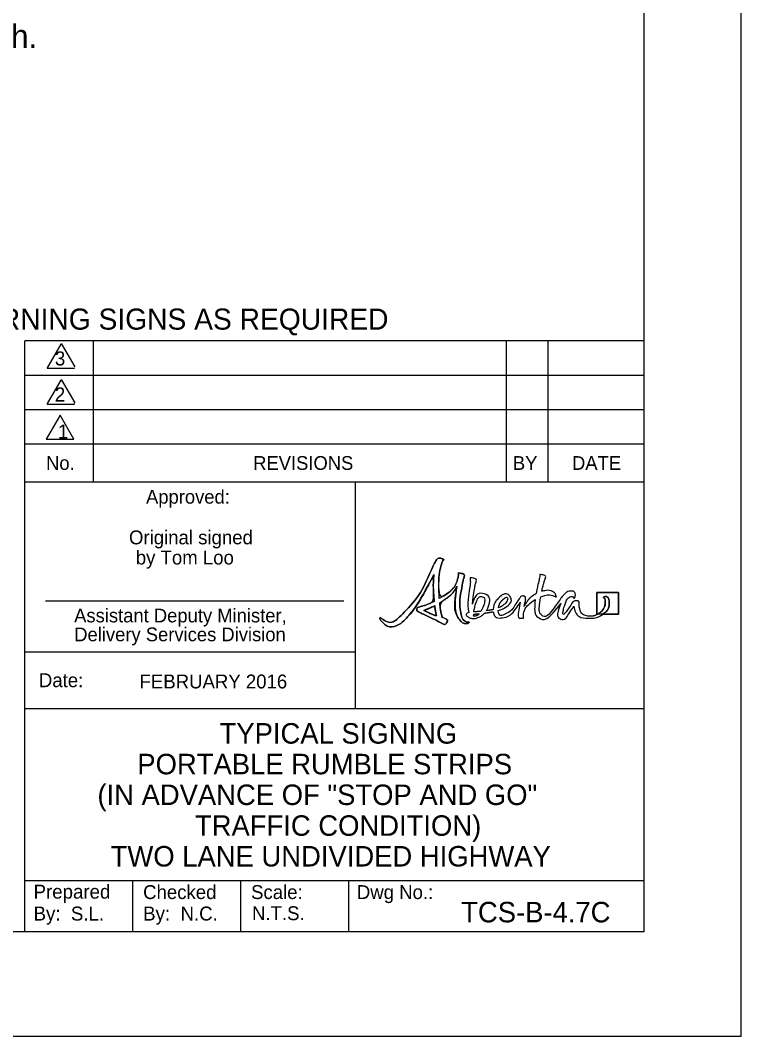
# Model space of a CAD drawing. Extents: x 1372 to 1588, y 125 to 404.
# Drawn here: x 1513.7 to 1588.1, y 125 to 229.9 of the extents above; entities that cross this region are included whole.
import ezdxf

# ---------------------------------------------------------------- set-up
doc = ezdxf.new("R2010")
doc.units = 0
for name, color, linetype in [('Level 1', 7, 'Continuous'), ('Level 10', 7, 'Continuous'), ('Level 22', 7, 'Continuous'), ('Level 44', 7, 'Continuous'), ('Level 45', 7, 'Continuous'), ('Level 53', 7, 'Continuous'), ('Level 60', 7, 'Continuous'), ('Level 63', 7, 'Continuous')]:
    doc.layers.add(name, color=color, linetype=linetype)

msp = doc.modelspace()

# ---------------------------------------------------------------- linework, layer by layer
at = {"layer": 'Level 1'}
for p, q in [((1514.18, 135.79), (1514.18, 182.27)), ((1548.25, 182.27), (1548.25, 158.85)), ((1514.18, 164.71), (1548.25, 164.71)), ((1514.18, 158.85), (1578.06, 158.85)), ((1514.18, 141.11), (1578.06, 141.11)), ((1525.32, 135.79), (1525.32, 141.11)), ((1536.45, 135.79), (1536.45, 141.11)), ((1547.59, 141.11), (1547.59, 135.79))]:
    msp.add_line(p, q, dxfattribs=at)
at = {"layer": 'Level 10'}
msp.add_line((1578.06, 182.27), (1578.06, 135.79), dxfattribs=at)
at = {"layer": 'Level 22'}
msp.add_line((1529.67, 135.79), (1529.67, 135.79), dxfattribs=at)
at = {"layer": 'Level 44'}
for p, q in [((1578.06, 196.82), (1514.18, 196.82)), ((1578.06, 193.27), (1514.18, 193.27)), ((1578.06, 189.72), (1514.18, 189.72)), ((1578.06, 186.18), (1514.18, 186.18)), ((1514.18, 182.27), (1578.06, 182.27))]:
    msp.add_line(p, q, dxfattribs=at)
msp.add_lwpolyline([(1517.8, 189.16), (1516.38, 186.69), (1519.22, 186.69)], close=True, dxfattribs=at)
at = {"layer": 'Level 45'}
msp.add_line((1548.25, 182.27), (1548.25, 182.27), dxfattribs=at)
at = {"layer": 'Level 53'}
msp.add_line((1573.82, 168.6), (1573.27, 168.6), dxfattribs=at)
msp.add_lwpolyline([(1573.82, 168.6), (1575.44, 168.6), (1575.44, 170.83), (1573.21, 170.83), (1573.21, 168.6), (1573.27, 168.6)], dxfattribs=at)
for points, degree in [([(1559.84, 167.79), (1559.6, 167.82), (1559.28, 168.15), (1559.19, 168.68), (1559.02, 169.65), (1559.12, 170.61), (1559.4, 172.03), (1559.45, 172.29), (1559.64, 172.76), (1559.05, 172.85), (1558.87, 172.88), (1558.97, 172.79), (1558.91, 172.54), (1558.69, 171.48), (1557.82, 170.72), (1556.95, 170.21), (1556.86, 171.42), (1556.9, 172.77), (1557.13, 173.59), (1557.32, 174.29), (1557.55, 174.16), (1557.27, 174.31), (1556.97, 174.46), (1556.65, 174.26), (1556.39, 173.74), (1556.13, 173.22), (1554.93, 170.4), (1553.02, 168.5), (1552.04, 167.53), (1551.16, 168.03), (1550.98, 168.18), (1550.83, 168.3), (1550.78, 168.12), (1550.96, 167.92), (1551.75, 167.07), (1552.91, 167.56), (1553.33, 167.98), (1554.49, 169.14), (1555.84, 171.64), (1556.39, 172.71), (1556.34, 172.11), (1556.32, 171.11), (1556.43, 169.93), (1555.84, 169.64), (1555.31, 169.47), (1555.06, 169.41), (1554.79, 169.34), (1554.62, 169.23), (1554.62, 169.1), (1554.61, 168.96), (1554.79, 168.85), (1555.06, 168.72), (1555.52, 168.5), (1556.9, 167.85), (1557.23, 167.65), (1557.52, 167.49), (1557.67, 167.62), (1557.75, 167.8), (1557.86, 168.03), (1557.56, 168.17), (1557.26, 168.26), (1557.14, 168.66), (1557.05, 169.19), (1556.99, 169.78), (1557.69, 170.21), (1558.38, 170.78), (1558.77, 171.5), (1558.67, 170.9), (1558.42, 168.87), (1559.06, 168.01), (1559.2, 167.82), (1559.51, 167.62), (1559.81, 167.65), (1559.96, 167.66), (1560.03, 167.76), (1560.02, 167.79), (1560, 167.82), (1559.92, 167.77), (1559.84, 167.79)], 3), ([(1556.95, 170.21), (1556.86, 171.42), (1556.9, 172.77), (1557.13, 173.59), (1557.32, 174.29), (1557.55, 174.16), (1557.27, 174.31), (1556.97, 174.46), (1556.65, 174.26), (1556.39, 173.74), (1556.13, 173.22), (1554.93, 170.4), (1553.02, 168.5), (1552.04, 167.53), (1551.16, 168.03), (1550.98, 168.18), (1550.83, 168.3), (1550.78, 168.12), (1550.96, 167.92), (1551.75, 167.07), (1552.91, 167.56), (1553.33, 167.98), (1554.49, 169.14), (1555.84, 171.64), (1556.39, 172.71)], 3), ([(1556.39, 172.71), (1556.34, 172.11), (1556.32, 171.11), (1556.43, 169.93)], 2), ([(1559.84, 167.79), (1559.6, 167.82), (1559.28, 168.15), (1559.19, 168.68), (1559.02, 169.65), (1559.12, 170.61), (1559.4, 172.03), (1559.45, 172.29), (1559.64, 172.76), (1559.05, 172.85), (1558.87, 172.88), (1558.97, 172.79), (1558.91, 172.54), (1558.69, 171.48), (1557.82, 170.72), (1556.95, 170.21)], 3), ([(1560.37, 169.63), (1560.42, 170.2), (1560.51, 170.89), (1560.64, 171.53), (1560.69, 171.8), (1560.88, 172.27), (1560.29, 172.36), (1560.11, 172.38), (1560.13, 172.3), (1560.15, 172.05), (1560.17, 171.71), (1559.8, 169.67), (1559.99, 168.77)], 3), ([(1567.53, 170.97), (1567.59, 171.27), (1567.67, 171.57), (1567.75, 171.86), (1567.82, 172.13), (1568.05, 172.6), (1567.47, 172.69), (1567.29, 172.71), (1567.36, 172.63), (1567.3, 172.38), (1567.19, 171.92), (1567.05, 171.33), (1566.95, 170.73)], 3), ([(1556.99, 169.78), (1557.69, 170.21), (1558.38, 170.78), (1558.77, 171.5)], 2), ([(1558.77, 171.5), (1558.67, 170.9), (1558.42, 168.87), (1559.06, 168.01), (1559.2, 167.82), (1559.51, 167.62), (1559.81, 167.65), (1559.96, 167.66), (1560.03, 167.76), (1560.02, 167.79), (1560, 167.82), (1559.92, 167.77), (1559.84, 167.79)], 3), ([(1567.42, 170.41), (1568.06, 170.66), (1568.59, 170.58), (1568.89, 170.44), (1569.04, 170.37), (1569.06, 170.38), (1569, 170.54), (1568.9, 170.78), (1568.39, 171.15), (1567.58, 170.98), (1567.56, 170.98), (1567.55, 170.97), (1567.53, 170.97)], 3), ([(1561.81, 168.97), (1562.22, 169.64), (1562.19, 170.55), (1561.58, 170.7), (1560.88, 170.88), (1560.52, 170.2), (1560.37, 169.63)], 3), ([(1560.52, 168.84), (1560.62, 169.55), (1560.99, 170.55), (1561.45, 170.39), (1561.72, 170.3), (1561.58, 169.46), (1561.24, 168.9)], 3), ([(1563.04, 168.99), (1563.13, 169.02), (1563.22, 169.05), (1563.29, 169.08), (1564.17, 169.47), (1564.48, 170.06), (1564.25, 170.42), (1564.04, 170.76), (1563.43, 170.66), (1562.95, 170.15), (1562.71, 169.9), (1562.53, 169.47), (1562.51, 169.08)], 3), ([(1565.71, 169.4), (1565.77, 169.68), (1565.85, 169.99), (1565.86, 170.19), (1565.87, 170.41), (1565.72, 170.46), (1565.66, 170.47), (1565.53, 170.51), (1565.38, 170.45), (1565.23, 170.24), (1564.88, 169.74), (1564.43, 168.95), (1563.75, 168.62), (1563.26, 168.38), (1563.05, 168.62), (1563.04, 168.99)], 3), ([(1563.51, 170.11), (1563.8, 170.38), (1563.95, 170.36), (1563.99, 170.29), (1564.07, 170.13), (1563.73, 169.57), (1563.06, 169.26)], 3), ([(1563.06, 169.26), (1563.12, 169.56), (1563.28, 169.89), (1563.51, 170.11)], 2), ([(1565.3, 169.84), (1565.25, 169.31), (1564.9, 168.13), (1565.49, 168.2), (1565.73, 168.22), (1565.63, 168.26), (1565.64, 168.46), (1565.69, 169.16), (1566.28, 169.76), (1566.86, 170.13)], 3), ([(1566.95, 170.73), (1566.47, 170.46), (1566.03, 170), (1565.71, 169.4)], 2), ([(1566.86, 170.13), (1566.76, 169.26), (1566.8, 168.49), (1567.19, 168.25), (1567.91, 167.8), (1568.93, 168.98), (1569.5, 169.71)], 3), ([(1572.58, 168.4), (1571.67, 168.4), (1571.43, 169.11), (1571.39, 169.46), (1571.36, 169.69), (1571.41, 170.03), (1571, 169.99), (1570.72, 169.96), (1570.46, 169.41), (1570.1, 168.94), (1569.8, 168.54), (1569.66, 168.58), (1569.73, 168.92), (1569.82, 169.35), (1570.18, 170.36), (1570.59, 170.43), (1570.78, 170.46), (1570.84, 170.13), (1570.93, 170.34), (1571.02, 170.55), (1570.94, 171), (1570.51, 171), (1570.22, 171), (1569.86, 170.68), (1569.57, 170.33), (1569.32, 170.01), (1568.03, 168.12), (1567.49, 168.53), (1567.24, 168.72), (1567.26, 169.5), (1567.42, 170.41)], 3), ([(1573.21, 170.83), (1573.21, 170.83), (1573.21, 168.6), (1573.21, 168.6), (1573.21, 168.6), (1573.27, 168.6), (1573.27, 168.6), (1573.75, 168.88), (1574.08, 169.44), (1574.08, 169.9), (1574.08, 170.29), (1573.87, 170.27), (1573.89, 170.32), (1573.96, 170.48), (1574.45, 170.39), (1574.48, 169.84), (1574.51, 169.36), (1574.26, 168.91), (1573.82, 168.6), (1573.82, 168.6), (1575.44, 168.6), (1575.44, 168.6), (1575.44, 168.6), (1575.44, 170.83), (1575.44, 170.83), (1575.44, 170.83), (1573.21, 170.83), (1573.21, 170.83)], 3), ([(1573.27, 168.6), (1573.75, 168.88), (1574.08, 169.44), (1574.08, 169.9), (1574.08, 170.29), (1573.87, 170.27), (1573.89, 170.32), (1573.96, 170.48), (1574.45, 170.39), (1574.48, 169.84), (1574.51, 169.36), (1574.26, 168.91), (1573.82, 168.6)], 3), ([(1556.43, 169.93), (1555.84, 169.64), (1555.31, 169.47), (1555.06, 169.41), (1554.79, 169.34), (1554.62, 169.23), (1554.62, 169.1), (1554.61, 168.96), (1554.79, 168.85), (1555.06, 168.72), (1555.52, 168.5), (1556.9, 167.85), (1557.23, 167.65), (1557.52, 167.49), (1557.67, 167.62), (1557.75, 167.8), (1557.86, 168.03), (1557.56, 168.17), (1557.26, 168.26)], 3), ([(1555.36, 169), (1555.67, 169.11), (1556.07, 169.28), (1556.48, 169.49)], 2), ([(1555.36, 169), (1555.67, 169.11), (1556.07, 169.28), (1556.48, 169.49), (1556.54, 169.02), (1556.6, 168.68), (1556.66, 168.42), (1556.36, 168.53), (1555.93, 168.71), (1555.36, 169)], 3), ([(1556.66, 168.42), (1556.36, 168.53), (1555.93, 168.71), (1555.36, 169)], 2), ([(1556.48, 169.49), (1556.54, 169.02), (1556.6, 168.68), (1556.66, 168.42)], 2), ([(1557.26, 168.26), (1557.14, 168.66), (1557.05, 169.19), (1556.99, 169.78)], 2), ([(1562.51, 169.08), (1562.31, 169.04), (1562.07, 169), (1561.81, 168.97)], 2), ([(1562.52, 168.86), (1562.57, 168.47), (1562.82, 168.17), (1563.42, 168.23), (1564.26, 168.3), (1565.01, 169.34), (1565.3, 169.84)], 3), ([(1569.5, 169.71), (1569.21, 169.07), (1569.05, 168.24), (1569.48, 168.11), (1569.98, 167.96), (1570.38, 168.8), (1570.85, 169.44)], 3), ([(1570.85, 169.44), (1570.9, 168.98), (1571.21, 168.19), (1572.44, 168.19), (1573, 168.19), (1573.47, 168.35), (1573.82, 168.6)], 3), ([(1559.99, 168.77), (1559.74, 168.69), (1559.64, 168.5), (1559.96, 168.31), (1560.19, 168.17), (1560.68, 168.12), (1561.17, 168.37), (1561.35, 168.45), (1561.5, 168.58), (1561.63, 168.72)], 3), ([(1560.45, 168.4), (1560.48, 168.43), (1560.5, 168.47), (1560.5, 168.52), (1560.5, 168.55), (1560.5, 168.58), (1560.5, 168.62)], 3), ([(1560.65, 168.41), (1560.57, 168.39), (1560.5, 168.4), (1560.45, 168.4)], 2), ([(1560.5, 168.62), (1560.63, 168.62), (1560.82, 168.64), (1561.06, 168.66)], 2), ([(1561.24, 168.9), (1561.01, 168.88), (1560.77, 168.86), (1560.52, 168.84)], 2), ([(1561.06, 168.66), (1560.94, 168.52), (1560.8, 168.43), (1560.65, 168.41)], 2), ([(1561.63, 168.72), (1561.92, 168.76), (1562.23, 168.81), (1562.52, 168.86)], 2), ([(1573.27, 168.6), (1573.06, 168.47), (1572.83, 168.4), (1572.58, 168.4)], 2)]:
    msp.add_open_spline(points, degree=degree, dxfattribs=at)
at = {"layer": 'Level 60'}
for p, q in [((1516.29, 169.99), (1547.11, 169.99)), ((1578.06, 135.79), (1578.06, 135.79)), ((1588.06, 124.98), (1588.06, 124.98))]:
    msp.add_line(p, q, dxfattribs=at)
for points in [[(1372.06, 403.98), (1588.06, 403.98), (1588.06, 124.98), (1372.06, 124.98)], [(1391.18, 393.17), (1578.06, 393.17), (1578.06, 135.79), (1391.18, 135.79)]]:
    msp.add_lwpolyline(points, close=True, dxfattribs=at)
at = {"layer": 'Level 63'}
for p, q in [((1514.18, 190.35), (1514.18, 196.82)), ((1521.27, 190.35), (1521.27, 196.82)), ((1563.86, 196.82), (1563.86, 182.27)), ((1568.17, 196.82), (1568.17, 182.27)), ((1514.18, 182.27), (1514.18, 190.35)), ((1521.27, 182.27), (1521.27, 190.35))]:
    msp.add_line(p, q, dxfattribs=at)
for points in [[(1517.88, 196.49), (1516.49, 194.06)], [(1519.37, 194.14), (1517.97, 196.57)], [(1516.49, 194.06), (1516.46, 194.02), (1519.3, 194.02), (1519.28, 194.06)], [(1517.88, 192.77), (1516.49, 190.35)], [(1519.37, 190.43), (1517.97, 192.85)], [(1516.49, 190.35), (1516.46, 190.3), (1519.3, 190.3), (1519.28, 190.35)]]:
    msp.add_lwpolyline(points, dxfattribs=at)

# ---------------------------------------------------------------- texts
at = {"layer": 'Level 1'}
for s, height, p in [('Date:', 1.434, (1515.62, 161.07)), ('Prepared', 1.441, (1515.07, 139.23)), ('Checked', 1.434, (1526.38, 139.19)), ('Scale:', 1.434, (1537.52, 139.19)), ('Dwg No.:', 1.434, (1548.44, 139.19)), ('By:  S.L.', 1.441, (1515.07, 136.97)), ('By:  N.C.', 1.441, (1526.38, 136.97)), ('    N.T.S.   ', 1.4336, (1535.49, 137.01))]:
    msp.add_text(s, height=height, rotation=360, dxfattribs=at).set_placement(p)
at = {"layer": 'Level 10'}
msp.add_text('90 km/h.', height=2.419, dxfattribs=at).set_placement((1503.05, 227.07))
for s, height, p in [('ADDITIONAL WARNING SIGNS AS REQUIRED', 2.177, (1488.62, 197.99)), ('TYPICAL SIGNING', 2.116, (1534.27, 155.24)), ('PORTABLE RUMBLE STRIPS', 2.116, (1525.78, 152.07)), ('(IN ADVANCE OF "STOP AND GO"', 2.116, (1521.66, 148.9)), ('TRAFFIC CONDITION)', 2.116, (1531.73, 145.72)), ('TWO LANE UNDIVIDED HIGHWAY ', 2.116, (1523.03, 142.55))]:
    msp.add_text(s, height=height, rotation=360, dxfattribs=at).set_placement(p)
at = {"layer": 'Level 44'}
for s, height, p in [('3', 1.45, (1517.27, 194.29)), ('2', 1.45, (1517.26, 190.57)), ('1', 1.45, (1517.58, 186.74)), ('No.', 1.419, (1516.36, 183.51)), ('REVISIONS', 1.419, (1537.74, 183.51)), ('BY', 1.419, (1564.55, 183.51)), ('DATE', 1.419, (1570.65, 183.51))]:
    msp.add_text(s, height=height, rotation=360, dxfattribs=at).set_placement(p)
at = {"layer": 'Level 60'}
for s, height, p in [('Approved:', 1.419, (1526.68, 180.02)), ('Original signed', 1.434, (1524.92, 175.82)), ('by Tom Loo', 1.434, (1525.62, 173.74)), ('Assistant Deputy Minister,', 1.4194, (1519.26, 167.76)), ('Delivery Services Division', 1.4194, (1519.27, 165.81)), ('FEBRUARY 2016', 1.434, (1526.01, 160.94)), ('TCS-B-4.7C', 2.116, (1559.21, 136.78))]:
    msp.add_text(s, height=height, dxfattribs=at).set_placement(p)

doc.saveas('drawing.dxf')
